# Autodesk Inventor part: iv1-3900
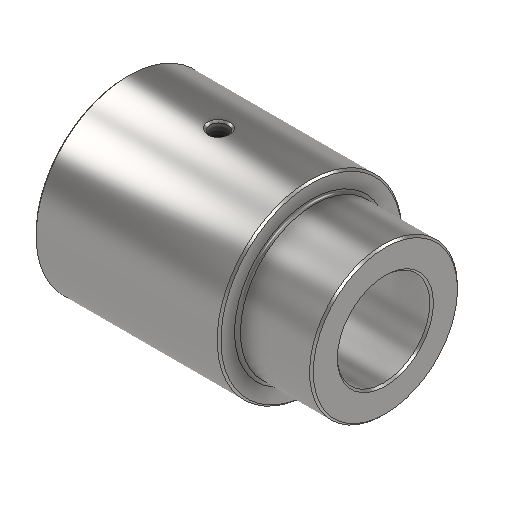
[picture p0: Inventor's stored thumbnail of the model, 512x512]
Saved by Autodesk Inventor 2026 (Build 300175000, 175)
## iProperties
Created: 2022-01
Part Number: iv1-3900
Material: Steel, Mild
Document SubType Name: Modeling
Designer: Lars Bertram Pedersen
Density: 7.85 g/cm^3
Appearance: Semi-Polished
Mass: 695.893 g
Surface Area: 187.438 cm^2
Volume: 88.6488 cm^3
Author: Lars Bertram Pedersen
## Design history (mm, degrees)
revolve "Revolution1" stored, may be unused: angle "d5" = 90 deg
fillet "Fillet1" dims "d6" = 0.8
chamfer "Chamfer1" distance "d7" = 0.5; stored, may be unused: second distance "d8" = 2, angle "d9" = 45 deg
workplane "Work Plane1"
sketch "Sketch2"
  geometry: L1 (25, 24.5)-(25, -24.5) reference; 3 further points
  constraints: 1 horizontal alignment, 1 midpoint
  dimensions: "d10" = 25 distance from line of L1 point (0, 0)
hole "Hole1" sketch "Sketch2" diameter "d11" = 4.917; stored, may be unused: countersink angle "d15" = 90 deg, drill point angle "d17" = 118 deg; dims "d12" = 12, "d13" = 4, "d14" = 2, "d16" = 17.1
chamfer "Chamfer2" distance "d18" = 0.5; stored, may be unused: second distance "d19" = 2, angle "d20" = 45 deg
body "Solid1"
sketch "Sketch1"
  geometry: L1 (0, 0)-(70, 0); L2 (0, 12.5)-(0, 25); L3 (0, 25)-(50, 25); L4 (50, 25)-(50, 20); L5 (50, 20)-(70, 20); L6 (70, 20)-(70, 12.5); L7 (70, 12.5)-(0, 12.5)
  constraints: 14 end point, 4 perpendicular, 2 horizontal, 2 vertical alignment, 1 vertical
  dimensions: "d0" = 25 diameter of L7 L1; "d1" = 70 distance of L1.start L1.end; "d2" = 50 distance of L2.end L3.end; "d3" = 50 diameter of L3 L1; "d4" = 40 diameter of L5 L1
